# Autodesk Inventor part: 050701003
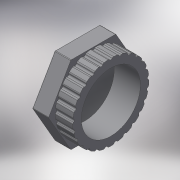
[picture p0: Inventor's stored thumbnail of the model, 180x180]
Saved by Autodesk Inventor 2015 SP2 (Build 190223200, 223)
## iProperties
Created: 2017-10
Part Number: 050701003
Material: Generic
Description: PLASSON THREADED CAP PVC 3/8"
Document SubType Name: Modeling
Designer: KIM
Density: 1 g/cm^3
Appearance: Default
Author: KIM
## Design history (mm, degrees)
derived "050701.ipt"
feature "Solid1::050701.ipt"
tag "TaggingFeature1"
body "Solid1"
other parameters: "d0" = 25, "d1" = 24.5, "d2" = 1, "d3" = 12, "d4" = 25, "d5" = 16, "d6" = 14.95, "d7" = 4.8, "d10" = 0, "d11" = 1, "d13" = 0, "d14" = 0.5, "d16" = 360 deg, "d18" = 0.25, "G_" = 14.95, "C_" = 25, "B_" = 12, "Lt_" = 16, "H_" = 25
